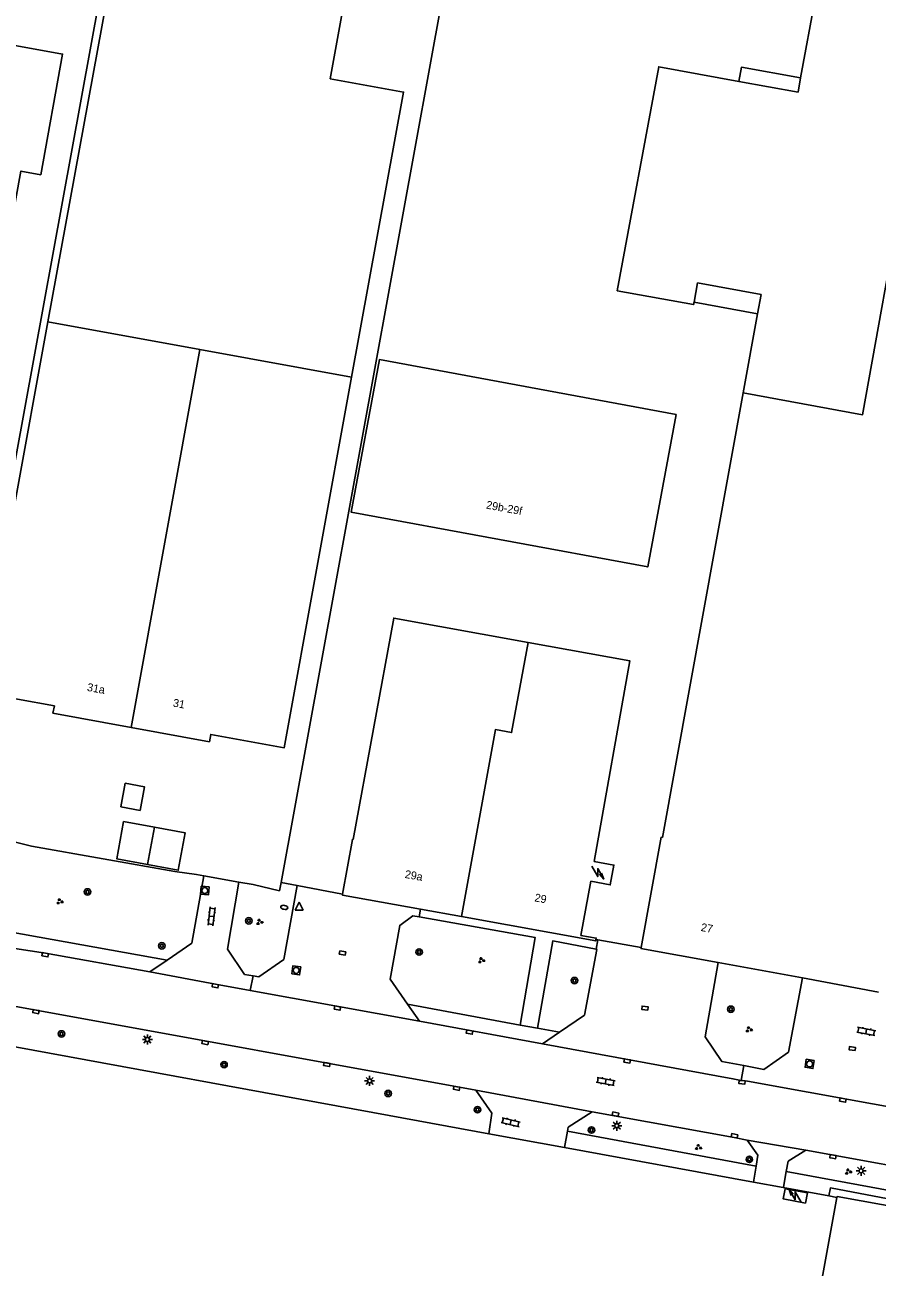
# Model space of a CAD drawing. Extents: x 130998 to 133001, y 398999 to 403002.
# Drawn here: x 131954.5 to 132061, y 399287.6 to 399442.9 of the extents above; entities that cross this region are included whole.
import ezdxf

# ---------------------------------------------------------------- set-up
doc = ezdxf.new("R2010")
doc.units = 0
for name, color, linetype in [('gg-afsc-hekwerk', 7, 'Continuous'), ('gg-anno-huisnummerreeks BGT', 7, 'Continuous'), ('gg-bbg-bijgebouw', 7, 'Continuous'), ('gg-bbg-gedigitaliseerde bijgebouw', 7, 'Continuous'), ('gg-bbg-hoofdgebouw', 7, 'Continuous'), ('gg-bbg-luifel en loopbrug', 7, 'Continuous'), ('gg-bbg-tussenscheiding', 7, 'Continuous'), ('gg-knt-verharding', 7, 'Continuous'), ('gg-knt-verharding nz', 7, 'Continuous'), ('gt-grn-groengrens', 7, 'Continuous'), ('gt-grn-weggrens', 7, 'Continuous'), ('gt-symb-boom', 7, 'Continuous'), ('gt-symb-brandkraan', 7, 'Continuous'), ('gt-symb-groenvak', 7, 'Continuous'), ('gt-symb-klinker verharding', 7, 'Continuous'), ('gt-symb-kolk', 7, 'Continuous'), ('gt-symb-kolk center center', 7, 'Continuous'), ('gt-symb-lichtmast', 7, 'Continuous'), ('gt-symb-rioolschacht', 7, 'Continuous'), ('gt-symb-trafo symbool', 7, 'Continuous'), ('gt-symb-waterafsluiter', 7, 'Continuous')]:
    doc.layers.add(name, color=color, linetype=linetype)

# ---------------------------------------------------------------- blocks, each defined once
blk = doc.blocks.new('gt0-BOOM')
at = {"layer": 'gt-symb-boom'}
for radius in [0.4, 0.2]:
    blk.add_circle((0, 0), radius, dxfattribs=at)
blk = doc.blocks.new('gt0-RS')
at = {"layer": 'gt-symb-rioolschacht'}
blk.add_lwpolyline([(-0.5, -0.5), (0.5, -0.5), (0.5, 0.5), (-0.5, 0.5)], close=True, dxfattribs=at)
blk.add_circle((0, 0), 0.375, dxfattribs=at)
blk = doc.blocks.new('gt0-KL1')
at = {"layer": 'gt-symb-klinker verharding'}
for p, q in [((-1.15, 0.3), (1.15, 0.3)), ((-1, -0.3), (-1, 0.3)), ((-0.5, 0.3), (-0.5, 0.45)), ((0, -0.3), (0, 0.3)), ((0.5, 0.3), (0.5, 0.45)), ((1, -0.3), (1, 0.3)), ((-1.15, -0.3), (1.15, -0.3)), ((-0.5, -0.45), (-0.5, -0.3)), ((0.5, -0.45), (0.5, -0.3))]:
    blk.add_line(p, q, dxfattribs=at)
blk = doc.blocks.new('gt0-GRVAK')
at = {"layer": 'gt-symb-groenvak'}
for p, q in [((-0.11, 0.19), (-0.23, 0.24)), ((-0.18, 0.15), (0.09, 0.15)), ((-0.09, 0.21), (-0.16, 0.32)), ((-0.05, 0.21), (-0.05, 0.39)), ((0, 0.21), (0.06, 0.32)), ((0.01, 0.19), (0.13, 0.24)), ((0.26, -0.05), (0.2, 0.06)), ((0.3, -0.05), (0.3, 0.13)), ((0.35, -0.05), (0.41, 0.06)), ((-0.24, -0.23), (-0.36, -0.18)), ((-0.32, -0.26), (-0.05, -0.26)), ((-0.23, -0.21), (-0.29, -0.09)), ((-0.18, -0.2), (-0.18, -0.02)), ((-0.14, -0.21), (-0.07, -0.09)), ((-0.12, -0.23), (0, -0.18)), ((0.24, -0.07), (0.12, -0.02)), ((0.17, -0.11), (0.44, -0.11)), ((0.37, -0.07), (0.49, -0.02))]:
    blk.add_line(p, q, dxfattribs=at)
blk = doc.blocks.new('gt0-HSP')
at = {"layer": 'gt-symb-trafo symbool'}
for points in [[(0.77, 0.75), (-0.53, 0), (0.47, 0), (-0.83, -0.75)], [(-0.22, -0.24), (-0.83, -0.75), (-0.08, -0.48)]]:
    blk.add_lwpolyline(points, dxfattribs=at)
blk = doc.blocks.new('gt0-BR')
at = {"layer": 'gt-symb-brandkraan'}
for centre, radius, start, end in [((-0.24, 0), 0.206, 107.5669, 252.4331), ((0.6, -2.66), 3, 106.892, 107.5669), ((0, -0.69), 0.938, 73.108, 106.892), ((-0.6, -2.66), 3, 72.4331, 73.108), ((0.24, 0), 0.206, 287.567, 72.4331), ((0.6, 2.66), 3, 252.4331, 253.108), ((0, 0.69), 0.938, 253.108, 286.8921), ((-0.6, 2.66), 3, 286.8921, 287.567)]:
    blk.add_arc(centre, radius, start, end, dxfattribs=at)
blk = doc.blocks.new('gt0-WAFSL')
at = {"layer": 'gt-symb-waterafsluiter'}
for p, q in [((-0.5, -0.33), (0, 0.67)), ((0, 0.67), (0.5, -0.33)), ((0.5, -0.33), (-0.5, -0.33))]:
    blk.add_line(p, q, dxfattribs=at)
blk = doc.blocks.new('gt0-KOLK')
at = {"layer": 'gt-symb-kolk'}
blk.add_lwpolyline([(0, 0), (0.37, 0), (0.37, 0.4), (-0.38, 0.4), (-0.38, 0), (0, 0)], dxfattribs=at)
blk = doc.blocks.new('gt0-KOLKCC')
at = {"layer": 'gt-symb-kolk center center'}
blk.add_lwpolyline([(-0.38, 0.2), (0.38, 0.2), (0.38, -0.2), (-0.38, -0.2)], close=True, dxfattribs=at)
blk = doc.blocks.new('gt0-LMAST')
at = {"layer": 'gt-symb-lichtmast'}
for p, q in [((-0.18, 0.17), (-0.45, 0.44)), ((-0.01, 0.25), (-0.01, 0.62)), ((0.17, 0.17), (0.44, 0.44)), ((-0.26, 0), (-0.63, 0)), ((-0.18, -0.18), (-0.45, -0.45)), ((-0.01, -0.25), (-0.01, -0.63)), ((0.44, -0.45), (0.17, -0.18)), ((0.24, 0), (0.62, 0))]:
    blk.add_line(p, q, dxfattribs=at)
blk.add_circle((-0.01, 0), 0.25, dxfattribs=at)

msp = doc.modelspace()

# ---------------------------------------------------------------- linework, layer by layer
at = {"layer": 'gg-afsc-hekwerk'}
for p, q in [((131968.12, 399469.82), (131944.82, 399342.16)), ((132009.58, 399462.26), (131986.49, 399335.68)), ((131981.23, 399335.74), (131976.83, 399336.51)), ((131986.49, 399335.68), (131988.5, 399335.3)), ((131988.5, 399335.3), (131994.18, 399334.22)), ((132026.07, 399328.53), (132025.84, 399328.57)), ((132031.49, 399327.57), (132026.07, 399328.53)), ((131906.68, 399323.68), (132000, 399306.58)), ((131906.68, 399323.68), (132000, 399306.58)), ((132000, 399306.58), (132012.47, 399304.3)), ((132000, 399306.58), (132012.47, 399304.3)), ((132012.47, 399304.3), (132021.92, 399302.57)), ((132012.47, 399304.3), (132021.92, 399302.57)), ((132021.92, 399302.57), (132045.54, 399298.24)), ((132021.92, 399302.57), (132045.54, 399298.24)), ((132045.54, 399298.24), (132049.24, 399297.57)), ((132045.54, 399298.24), (132049.24, 399297.57)), ((132054.96, 399296.52), (132049.24, 399297.57)), ((132054.96, 399296.52), (132049.24, 399297.57)), ((132055.96, 399296.34), (132054.96, 399296.52)), ((132055.96, 399296.34), (132054.96, 399296.52))]:
    msp.add_line(p, q, dxfattribs=at)
for points in [[(131976.83, 399336.51), (131975.93, 399336.67), (131973.24, 399337.05), (131955.33, 399340.22), (131953.5, 399340.67), (131951.29, 399341.12)], [(131981.23, 399335.74), (131983.03, 399335.42), (131986.29, 399334.66), (131986.49, 399335.68)]]:
    msp.add_lwpolyline(points, dxfattribs=at)
at = {"layer": 'gg-bbg-bijgebouw'}
msp.add_lwpolyline([(132052.04, 399295.63), (132052.27, 399296.9), (132049.47, 399297.41), (132049.24, 399296.15), (132052.04, 399295.63)], dxfattribs=at)
at = {"layer": 'gg-bbg-gedigitaliseerde bijgebouw'}
msp.add_line((131969.81, 399337.93), (131970.67, 399342.59), dxfattribs=at)
msp.add_lwpolyline([(131969.81, 399337.93), (131965.97, 399338.65), (131966.83, 399343.3), (131970.67, 399342.59)], dxfattribs=at)
at = {"layer": 'gg-bbg-hoofdgebouw'}
for p, q in [((132051.42, 399436.22), (132053.8, 399449.24)), ((132046.04, 399406.74), (132044.24, 399396.85)), ((132009.04, 399331.42), (132003.9, 399332.35)), ((132051.67, 399323.76), (132041.13, 399325.67)), ((132051.67, 399323.76), (132061.16, 399322)), ((132055.98, 399296.46), (132055.96, 399296.34)), ((132055.98, 399296.46), (132069.25, 399294.03))]:
    msp.add_line(p, q, dxfattribs=at)
for points in [[(131995.31, 399398.82), (132001.8, 399434.46), (131992.64, 399436.12), (131994.73, 399447.61), (131975.19, 399451.2), (131975.02, 399450.29), (131965.82, 399451.96), (131957.35, 399405.73)], [(131910.76, 399356.52), (131940.54, 399351.04), (131946.17, 399381.93), (131946.7, 399381.84), (131946.74, 399382.05), (131946.27, 399382.14), (131954, 399424.57), (131956.46, 399424.12), (131959.2, 399439.2), (131939.24, 399442.8), (131938.34, 399437.88), (131926.05, 399440.13), (131916.43, 399387.57), (131915.94, 399387.66), (131915.9, 399387.46), (131916.44, 399387.36), (131910.76, 399356.52)], [(132028.5, 399409.62), (132033.68, 399437.62), (132043.69, 399435.79)], [(132043.69, 399435.79), (132051.09, 399434.44), (132051.42, 399436.22)], [(132038.1, 399408.18), (132038.54, 399410.6), (132046.48, 399409.15), (132046.04, 399406.74)], [(132028.5, 399409.62), (132038.05, 399407.89), (132038.1, 399408.18)], [(131957.35, 399405.73), (131948.88, 399359.44), (131958.17, 399357.75), (131958, 399356.85), (131967.78, 399355.06)], [(132035.85, 399394.18), (132032.31, 399375.12), (131995.25, 399381.96), (131998.79, 399401.02), (132035.85, 399394.18)], [(131967.78, 399355.06), (131977.55, 399353.28), (131977.72, 399354.19), (131986.89, 399352.52), (131995.31, 399398.82)], [(132044.24, 399396.85), (132034.15, 399341.31), (132033.99, 399341.34), (132031.49, 399327.57)], [(131995.52, 399341.05), (132000.57, 399368.73), (132017.37, 399365.68)], [(132017.37, 399365.68), (132030.08, 399363.37), (132025.62, 399338.33), (132028.08, 399337.86), (132027.62, 399335.39), (132025.19, 399335.85)], [(131994.18, 399334.22), (131995.42, 399341.07), (131995.52, 399341.05)], [(132025.84, 399328.57), (132025.87, 399328.74), (132023.96, 399329.08), (132025.19, 399335.85)], [(132003.9, 399332.35), (131994.16, 399334.11), (131994.18, 399334.22)], [(132025.84, 399328.57), (132025.81, 399328.39), (132009.04, 399331.42)], [(132041.13, 399325.67), (132031.47, 399327.43), (132031.49, 399327.57)], [(132055.96, 399296.34), (132050.02, 399263.79), (132050.3, 399263.74)]]:
    msp.add_lwpolyline(points, dxfattribs=at)
at = {"layer": 'gg-bbg-luifel en loopbrug'}
msp.add_line((132038.1, 399408.18), (132046.04, 399406.74), dxfattribs=at)
for points in [[(132043.69, 399435.79), (132044.01, 399437.56), (132051.42, 399436.22)], [(131966.47, 399345.15), (131967.02, 399348.08), (131969.43, 399347.64), (131968.89, 399344.7), (131966.47, 399345.15)], [(131970.67, 399342.59), (131974.52, 399341.88), (131973.65, 399337.22), (131969.81, 399337.93)]]:
    msp.add_lwpolyline(points, dxfattribs=at)
at = {"layer": 'gg-bbg-tussenscheiding'}
for p, q in [((131957.35, 399405.73), (131976.36, 399402.27)), ((131967.78, 399355.06), (131976.36, 399402.27)), ((131976.36, 399402.27), (131995.31, 399398.82))]:
    msp.add_line(p, q, dxfattribs=at)
for points in [[(132064.36, 399423.02), (132059.15, 399394.13), (132044.24, 399396.85)], [(132017.37, 399365.68), (132015.31, 399354.42), (132013.28, 399354.8), (132009.04, 399331.42)]]:
    msp.add_lwpolyline(points, dxfattribs=at)
at = {"layer": 'gg-knt-verharding'}
for p, q in [((131975.33, 399328.09), (131976.83, 399336.51)), ((131979.8, 399327.35), (131981.23, 399335.74)), ((131986.85, 399326.06), (131988.5, 399335.3)), ((132003.77, 399331.4), (132002.98, 399331.54)), ((131952.56, 399329.53), (131972.25, 399325.98)), ((131972.25, 399325.98), (131975.33, 399328.09)), ((132002.31, 399320.47), (132016.38, 399317.88)), ((132016.38, 399317.88), (132018.52, 399317.49)), ((132018.52, 399317.49), (132021.28, 399316.98)), ((132022.29, 399304.63), (132021.92, 399302.57)), ((132045.54, 399298.24), (132045.87, 399300.26)), ((132049.26, 399297.63), (132049.62, 399299.57)), ((132049.26, 399297.63), (132049.24, 399297.57))]:
    msp.add_line(p, q, dxfattribs=at)
for points in [[(132002.98, 399331.54), (132001.32, 399330.33), (132000.11, 399323.61), (132002.31, 399320.47)], [(132016.38, 399317.88), (132018.25, 399328.8), (132003.77, 399331.4)], [(132018.52, 399317.49), (132020.44, 399328.39), (132025.86, 399327.34)], [(131979.8, 399327.35), (131981.93, 399324.21), (131983, 399324.02)], [(131983, 399324.02), (131983.74, 399323.9), (131986.85, 399326.06)], [(132025.86, 399327.34), (132025.94, 399327.32), (132024.4, 399319.12), (132021.28, 399316.98)], [(132044.33, 399312.8), (132041.57, 399313.33), (132039.48, 399316.4), (132041.13, 399325.67)], [(132051.67, 399323.76), (132049.91, 399314.5), (132046.8, 399312.33), (132044.33, 399312.8)], [(131942.96, 399322.08), (131955.9, 399319.75), (132010.82, 399309.74)], [(132010.82, 399309.74), (132012.84, 399306.87), (132012.47, 399304.3)], [(132025.36, 399307.05), (132022.37, 399305.1), (132022.29, 399304.63)], [(132044.74, 399303.49), (132043.11, 399303.84), (132025.36, 399307.05)], [(132045.87, 399300.26), (132046.09, 399301.6), (132044.74, 399303.49)], [(132049.62, 399299.57), (132049.85, 399300.85), (132052.08, 399302.25)], [(132072.41, 399298.58), (132071.37, 399298.73), (132052.08, 399302.25)]]:
    msp.add_lwpolyline(points, dxfattribs=at)
at = {"layer": 'gg-knt-verharding nz'}
for p, q in [((131972.25, 399325.98), (131970.11, 399324.51)), ((131982.65, 399322.2), (132003.81, 399318.34)), ((132002.31, 399320.47), (132003.81, 399318.34)), ((132019.17, 399315.53), (132003.81, 399318.34)), ((132021.28, 399316.98), (132019.17, 399315.53)), ((132010.82, 399309.74), (132025.36, 399307.05)), ((132044.74, 399303.49), (132052.08, 399302.25))]:
    msp.add_line(p, q, dxfattribs=at)
for points in [[(131953.22, 399327.46), (131957.05, 399326.86), (131970.11, 399324.51)], [(131982.65, 399322.2), (131978.31, 399322.98), (131970.11, 399324.51)], [(132043.97, 399310.96), (132042.96, 399311.17), (132019.17, 399315.53)], [(132067.97, 399306.65), (132044.79, 399310.86), (132044.11, 399310.93), (132043.97, 399310.96)]]:
    msp.add_lwpolyline(points, dxfattribs=at)
at = {"layer": 'gt-grn-groengrens'}
for p, q in [((132045.87, 399300.26), (132022.29, 399304.63)), ((132074.07, 399295.03), (132049.62, 399299.57))]:
    msp.add_line(p, q, dxfattribs=at)
msp.add_lwpolyline([(132070.16, 399294.18), (132070.21, 399294.67), (132055.14, 399297.53), (132054.96, 399296.52)], dxfattribs=at)
at = {"layer": 'gt-grn-weggrens'}
for p, q in [((132003.9, 399332.35), (132003.77, 399331.4)), ((132025.86, 399327.34), (132026.07, 399328.53)), ((131982.65, 399322.2), (131983, 399324.02)), ((132043.97, 399310.96), (132044.33, 399312.8))]:
    msp.add_line(p, q, dxfattribs=at)

# ---------------------------------------------------------------- block references
at = {"layer": 'gt-symb-boom'}
for p in [(131962.31, 399334.51), (131982.47, 399330.9), (131971.6, 399327.77), (132003.75, 399327), (132023.16, 399323.43), (132042.7, 399319.85), (131959.06, 399316.77), (131979.38, 399312.93), (131999.88, 399309.33), (132011.04, 399307.3), (132025.29, 399304.76), (132045.01, 399301.09)]:
    msp.add_blockref('gt0-BOOM', p, dxfattribs=at)
at = {"layer": 'gt-symb-brandkraan', "rotation": -9.613025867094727}
msp.add_blockref('gt0-BR', (131986.9, 399332.58), dxfattribs=at)
at = {"layer": 'gt-symb-groenvak'}
for p in [(131958.83, 399333.31), (131983.8, 399330.74), (132011.52, 399325.95), (132044.95, 399317.32), (132057.36, 399299.56)]:
    msp.add_blockref('gt0-GRVAK', p, dxfattribs=at)
at = {"layer": 'gt-symb-groenvak', "rotation": -9.905079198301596}
msp.add_blockref('gt0-GRVAK', (132038.62, 399302.59), dxfattribs=at)
at = {"layer": 'gt-symb-klinker verharding'}
for p, rotation in [((131977.81, 399331.46), -97.181878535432), ((132059.61, 399317.08), -10.781616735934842), ((132027.06, 399310.83), -10.30997039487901), ((132015.18, 399305.73), -13.174926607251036)]:
    msp.add_blockref('gt0-KL1', p, dxfattribs=dict(at, rotation=rotation))
at = {"layer": 'gt-symb-kolk'}
for p, rotation in [((131957.06, 399326.86), 169.3979417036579), ((131978.31, 399322.98), 169.63367739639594), ((131955.9, 399319.75), 169.63367739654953), ((131993.57, 399320.19), 169.80279442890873), ((132010.08, 399317.18), 169.69002960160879), ((131977.04, 399315.88), 169.74640197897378), ((132029.78, 399313.58), 169.63367739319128), ((131992.25, 399313.14), 169.63367739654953), ((132044.11, 399310.93), 174.48902304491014), ((132008.46, 399310.17), 169.69002960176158), ((132056.73, 399308.7), 169.74640197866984), ((132028.26, 399306.55), -10.30997039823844), ((132043.11, 399303.84), -11.950647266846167), ((132055.42, 399301.23), -10.30997039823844)]:
    msp.add_blockref('gt0-KOLK', p, dxfattribs=dict(at, rotation=rotation))
at = {"layer": 'gt-symb-kolk center center'}
for p, rotation in [((131994.17, 399326.88), -9.15139601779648), ((132031.97, 399319.99), 173.0525893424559), ((132057.87, 399314.94), 172.41293093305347)]:
    msp.add_blockref('gt0-KOLKCC', p, dxfattribs=dict(at, rotation=rotation))
at = {"layer": 'gt-symb-lichtmast'}
for p in [(131969.8, 399316.07), (131997.57, 399310.9), (132028.46, 399305.3), (132058.99, 399299.66)]:
    msp.add_blockref('gt0-LMAST', p, dxfattribs=at)
at = {"layer": 'gt-symb-rioolschacht'}
for p, rotation in [((131976.97, 399334.68), -95.16330681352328), ((131988.39, 399324.71), -7.814180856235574), ((132052.54, 399313.02), 170.44347238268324)]:
    msp.add_blockref('gt0-RS', p, dxfattribs=dict(at, rotation=rotation))
at = {"layer": 'gt-symb-trafo symbool'}
for p, rotation in [((132026.06, 399336.95), 90), ((132050.73, 399296.51), -90.00000000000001)]:
    msp.add_blockref('gt0-HSP', p, dxfattribs=dict(at, rotation=rotation))
at = {"layer": 'gt-symb-waterafsluiter'}
msp.add_blockref('gt0-WAFSL', (131988.76, 399332.55), dxfattribs=at)

# ---------------------------------------------------------------- texts
at = {"layer": 'gg-anno-huisnummerreeks BGT'}
for s, rotation, p in [('29b-29f', 349.5, (132012.06, 399382.42)), ('31a', 349.6, (131962.2, 399359.64)), ('31', 349.6, (131972.93, 399357.68)), ('29a', 349.7, (132001.9, 399336.27)), ('29', 349.7, (132018.11, 399333.34)), ('27', 349.7, (132038.89, 399329.64))]:
    msp.add_text(s, height=1, rotation=rotation, dxfattribs=at).set_placement(p)

doc.saveas('drawing.dxf')
